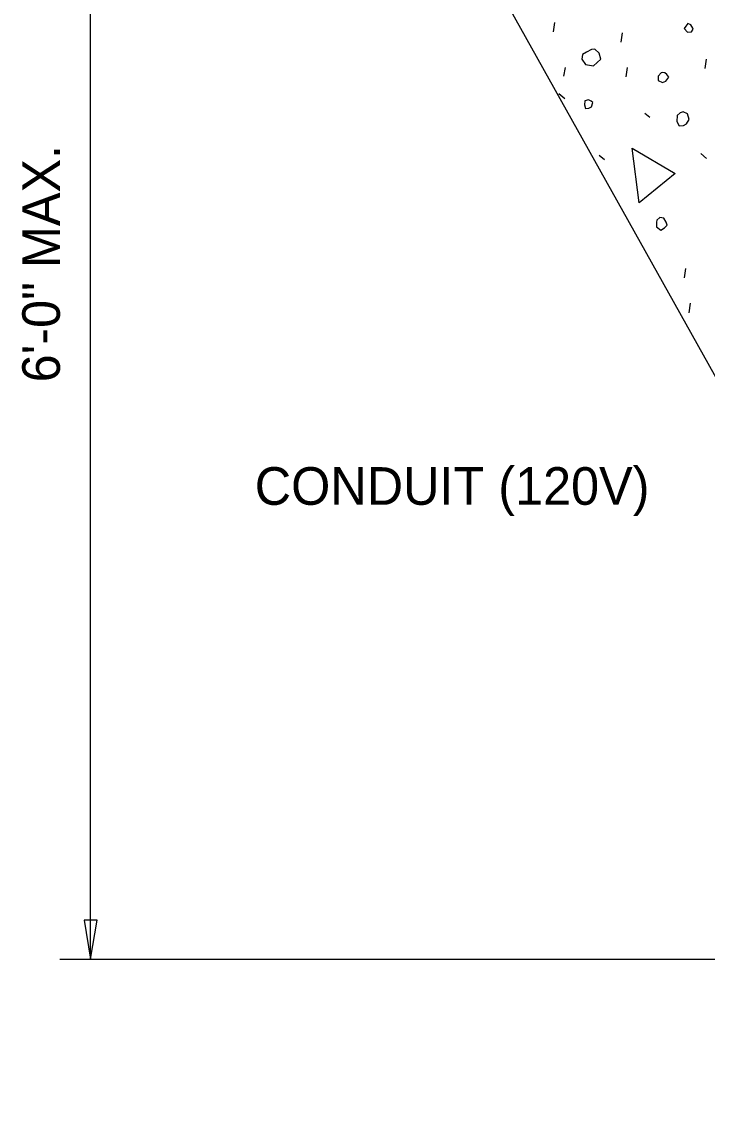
# Model space of a CAD drawing. Extents: x -1660015.2 to -1659984.9, y 2580594.2 to 2580616.7.
# Drawn here: x -1660013.205 to -1660010.453, y 2580605.711 to 2580610.058 of the extents above; entities that cross this region are included whole.
import ezdxf

# ---------------------------------------------------------------- set-up
doc = ezdxf.new("R2010")
doc.units = 0
for name, color, linetype in [('Miscellaneous', 7, 'Continuous'), ('Miscellaneous3', 7, 'Continuous'), ('PlotBorder_dp', 7, 'Continuous'), ('SheetLines_dp', 7, 'Continuous')]:
    doc.layers.add(name, color=color, linetype=linetype)

msp = doc.modelspace()

# ---------------------------------------------------------------- linework, layer by layer
at = {"layer": 'Miscellaneous'}
for p, q in [((-1660011.071, 2580610.017), (-1660011.0655, 2580610.0547)), ((-1660010.7986, 2580609.9761), (-1660010.7932, 2580610.0138)), ((-1660011.0286, 2580609.8394), (-1660011.0225, 2580609.8747)), ((-1660010.7793, 2580609.8364), (-1660010.7738, 2580609.874)), ((-1660010.4621, 2580609.8696), (-1660010.4566, 2580609.9073)), ((-1660011.0486, 2580609.7694), (-1660011.0252, 2580609.7497)), ((-1660010.704, 2580609.6909), (-1660010.6844, 2580609.6754)), ((-1660010.4794, 2580609.5285), (-1660010.456, 2580609.5089)), ((-1660010.8868, 2580609.5228), (-1660010.8665, 2580609.505)), ((-1660010.545, 2580609.0295), (-1660010.5395, 2580609.0672)), ((-1660010.5256, 2580608.8898), (-1660010.5202, 2580608.9274))]:
    msp.add_line(p, q, dxfattribs=at)
for points in [[(-1660010.5466, 2580610.0307), (-1660010.5324, 2580610.0164), (-1660010.5173, 2580610.0178), (-1660010.5096, 2580610.0277), (-1660010.5109, 2580610.0325), (-1660010.5196, 2580610.0457), (-1660010.5312, 2580610.0504), (-1660010.5389, 2580610.0405), (-1660010.5466, 2580610.0307)], [(-1660010.9563, 2580609.908), (-1660010.9426, 2580609.8858), (-1660010.9104, 2580609.8815), (-1660010.8811, 2580609.9074), (-1660010.8876, 2580609.9316), (-1660010.9048, 2580609.9476), (-1660010.9176, 2580609.9468), (-1660010.938, 2580609.9362), (-1660010.9536, 2580609.9268), (-1660010.9563, 2580609.908)], [(-1660010.6508, 2580609.8397), (-1660010.6511, 2580609.8215), (-1660010.6333, 2580609.8133), (-1660010.6195, 2580609.8196), (-1660010.6082, 2580609.8356), (-1660010.6163, 2580609.8464), (-1660010.6231, 2580609.8523), (-1660010.634, 2580609.8546), (-1660010.6389, 2580609.8533), (-1660010.6508, 2580609.8397)], [(-1660010.946, 2580609.7244), (-1660010.9421, 2580609.7099), (-1660010.9294, 2580609.7107), (-1660010.9179, 2580609.7164), (-1660010.9122, 2580609.7335), (-1660010.9189, 2580609.7394), (-1660010.9305, 2580609.7441), (-1660010.945, 2580609.7402), (-1660010.946, 2580609.7244)], [(-1660010.5747, 2580609.6815), (-1660010.5761, 2580609.6578), (-1660010.5661, 2580609.6398), (-1660010.5486, 2580609.6419), (-1660010.5372, 2580609.6476), (-1660010.5265, 2580609.666), (-1660010.5324, 2580609.6877), (-1660010.5501, 2580609.6959), (-1660010.5622, 2580609.6926), (-1660010.5747, 2580609.6815)], [(-1660010.7265, 2580609.3303), (-1660010.7544, 2580609.5505), (-1660010.5823, 2580609.4491), (-1660010.7265, 2580609.3303)], [(-1660010.6567, 2580609.2532), (-1660010.657, 2580609.235), (-1660010.6404, 2580609.2214), (-1660010.6247, 2580609.2307), (-1660010.6146, 2580609.2412), (-1660010.6178, 2580609.2533), (-1660010.6272, 2580609.2689), (-1660010.6436, 2580609.2722), (-1660010.6562, 2580609.2611), (-1660010.6567, 2580609.2532)]]:
    msp.add_lwpolyline(points, dxfattribs=at)
at = {"layer": 'Miscellaneous3'}
msp.add_line((-1660008.7906, 2580605.7114), (-1660012.2404, 2580611.8935), dxfattribs=at)
at = {"layer": 'SheetLines_dp'}
for p, q in [((-1660012.9281, 2580606.2947), (-1660012.9281, 2580611.9975)), ((-1660013.0517, 2580606.2947), (-1660010.3859, 2580606.2947))]:
    msp.add_line(p, q, dxfattribs=at)
msp.add_lwpolyline([(-1660012.9281, 2580606.2946), (-1660012.9017, 2580606.4508), (-1660012.9546, 2580606.4508)], close=True, dxfattribs=at)

# ---------------------------------------------------------------- texts
at = {"layer": 'PlotBorder_dp'}
msp.add_text('6\'-0" MAX.', height=0.1512, rotation=90, dxfattribs=at).set_placement((-1660013.0513, 2580608.6102))
msp.add_text('CONDUIT (120V)', height=0.1512, dxfattribs=at).set_placement((-1660012.2694, 2580608.1184))

doc.saveas('drawing.dxf')
